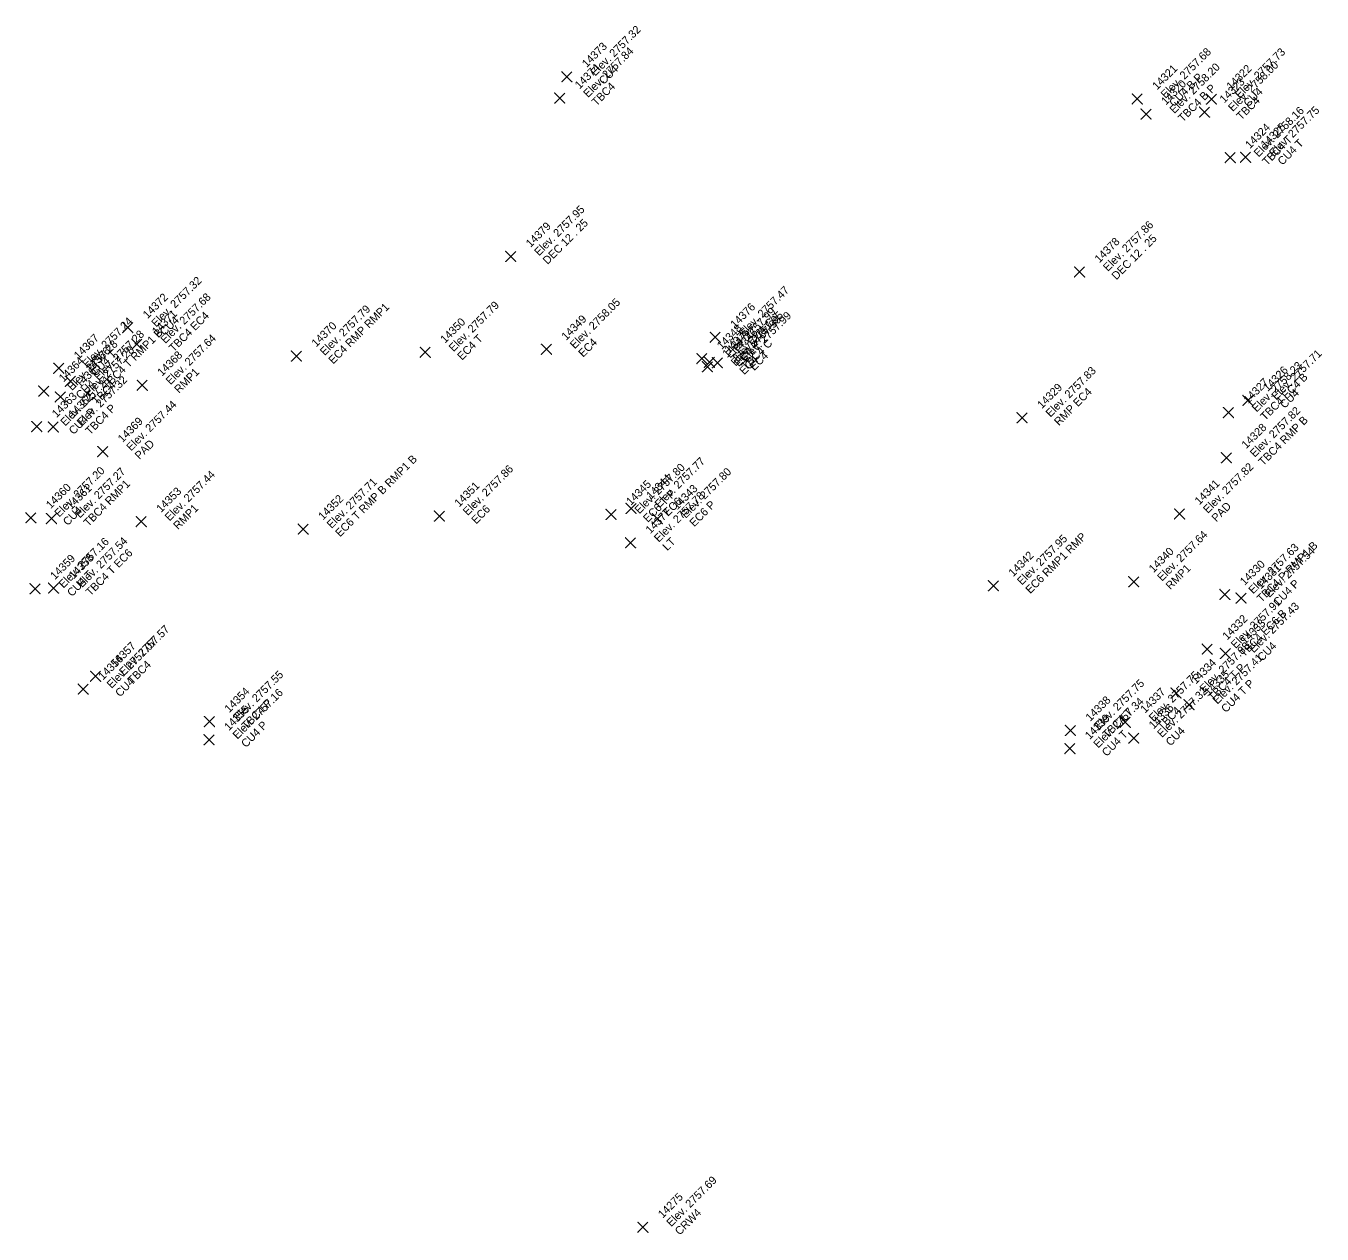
# Model space of a CAD drawing. Extents: x 2493999 to 2503109, y 700767 to 706646.
# Drawn here: x 2502364.97 to 2502403.84, y 703196.92 to 703233.16 of the extents above; entities that cross this region are included whole.
import ezdxf

# ---------------------------------------------------------------- set-up
doc = ezdxf.new("R2010")
doc.units = 0
doc.layers.add('ALG_CL_BLUE_Horiz', color=7, linetype='Continuous')
doc.layers.add('DES_SURFACE_Existing-Ground', color=7, linetype='Continuous')

msp = doc.modelspace()

# ---------------------------------------------------------------- linework, layer by layer
at = {"layer": 'ALG_CL_BLUE_Horiz'}
for points in [[(2502381.19, 703231.638), (2502381.04, 703231.788), (2502381.19, 703231.638), (2502381.04, 703231.488), (2502381.19, 703231.638), (2502381.34, 703231.488), (2502381.19, 703231.638), (2502381.34, 703231.788)], [(2502380.974, 703230.996), (2502380.824, 703231.146), (2502380.974, 703230.996), (2502380.824, 703230.846), (2502380.974, 703230.996), (2502381.124, 703230.846), (2502380.974, 703230.996), (2502381.124, 703231.146)], [(2502398.294, 703230.973), (2502398.144, 703231.123), (2502398.294, 703230.973), (2502398.144, 703230.823), (2502398.294, 703230.973), (2502398.444, 703230.823), (2502398.294, 703230.973), (2502398.444, 703231.123)], [(2502400.52, 703230.968), (2502400.37, 703231.118), (2502400.52, 703230.968), (2502400.37, 703230.818), (2502400.52, 703230.968), (2502400.67, 703230.818), (2502400.52, 703230.968), (2502400.67, 703231.118)], [(2502398.56, 703230.515), (2502398.41, 703230.665), (2502398.56, 703230.515), (2502398.41, 703230.365), (2502398.56, 703230.515), (2502398.71, 703230.365), (2502398.56, 703230.515), (2502398.71, 703230.665)], [(2502400.313, 703230.574), (2502400.163, 703230.724), (2502400.313, 703230.574), (2502400.163, 703230.424), (2502400.313, 703230.574), (2502400.463, 703230.424), (2502400.313, 703230.574), (2502400.463, 703230.724)], [(2502401.082, 703229.209), (2502400.932, 703229.359), (2502401.082, 703229.209), (2502400.932, 703229.059), (2502401.082, 703229.209), (2502401.232, 703229.059), (2502401.082, 703229.209), (2502401.232, 703229.359)], [(2502401.545, 703229.22), (2502401.395, 703229.37), (2502401.545, 703229.22), (2502401.395, 703229.07), (2502401.545, 703229.22), (2502401.695, 703229.07), (2502401.545, 703229.22), (2502401.695, 703229.37)], [(2502379.507, 703226.246), (2502379.357, 703226.396), (2502379.507, 703226.246), (2502379.357, 703226.096), (2502379.507, 703226.246), (2502379.657, 703226.096), (2502379.507, 703226.246), (2502379.657, 703226.396)], [(2502396.564, 703225.783), (2502396.414, 703225.933), (2502396.564, 703225.783), (2502396.414, 703225.633), (2502396.564, 703225.783), (2502396.714, 703225.633), (2502396.564, 703225.783), (2502396.714, 703225.933)], [(2502368.02, 703224.111), (2502367.87, 703224.261), (2502368.02, 703224.111), (2502367.87, 703223.961), (2502368.02, 703224.111), (2502368.17, 703223.961), (2502368.02, 703224.111), (2502368.17, 703224.261)], [(2502368.295, 703223.617), (2502368.145, 703223.767), (2502368.295, 703223.617), (2502368.145, 703223.467), (2502368.295, 703223.617), (2502368.445, 703223.467), (2502368.295, 703223.617), (2502368.445, 703223.767)], [(2502385.637, 703223.823), (2502385.487, 703223.973), (2502385.637, 703223.823), (2502385.487, 703223.673), (2502385.637, 703223.823), (2502385.787, 703223.673), (2502385.637, 703223.823), (2502385.787, 703223.973)], [(2502373.08, 703223.257), (2502372.93, 703223.407), (2502373.08, 703223.257), (2502372.93, 703223.107), (2502373.08, 703223.257), (2502373.23, 703223.107), (2502373.08, 703223.257), (2502373.23, 703223.407)], [(2502376.942, 703223.372), (2502376.792, 703223.522), (2502376.942, 703223.372), (2502376.792, 703223.222), (2502376.942, 703223.372), (2502377.092, 703223.222), (2502376.942, 703223.372), (2502377.092, 703223.522)], [(2502380.575, 703223.461), (2502380.425, 703223.611), (2502380.575, 703223.461), (2502380.425, 703223.311), (2502380.575, 703223.461), (2502380.725, 703223.311), (2502380.575, 703223.461), (2502380.725, 703223.611)], [(2502385.237, 703223.182), (2502385.087, 703223.332), (2502385.237, 703223.182), (2502385.087, 703223.032), (2502385.237, 703223.182), (2502385.387, 703223.032), (2502385.237, 703223.182), (2502385.387, 703223.332)], [(2502365.952, 703222.892), (2502365.802, 703223.042), (2502365.952, 703222.892), (2502365.802, 703222.742), (2502365.952, 703222.892), (2502366.102, 703222.742), (2502365.952, 703222.892), (2502366.102, 703223.042)], [(2502385.403, 703222.939), (2502385.253, 703223.089), (2502385.403, 703222.939), (2502385.253, 703222.789), (2502385.403, 703222.939), (2502385.553, 703222.789), (2502385.403, 703222.939), (2502385.553, 703223.089)], [(2502385.462, 703223.071), (2502385.312, 703223.221), (2502385.462, 703223.071), (2502385.312, 703222.921), (2502385.462, 703223.071), (2502385.612, 703222.921), (2502385.462, 703223.071), (2502385.612, 703223.221)], [(2502385.705, 703223.06), (2502385.555, 703223.21), (2502385.705, 703223.06), (2502385.555, 703222.91), (2502385.705, 703223.06), (2502385.855, 703222.91), (2502385.705, 703223.06), (2502385.855, 703223.21)], [(2502366.299, 703222.504), (2502366.149, 703222.654), (2502366.299, 703222.504), (2502366.149, 703222.354), (2502366.299, 703222.504), (2502366.449, 703222.354), (2502366.299, 703222.504), (2502366.449, 703222.654)], [(2502368.454, 703222.381), (2502368.304, 703222.531), (2502368.454, 703222.381), (2502368.304, 703222.231), (2502368.454, 703222.381), (2502368.604, 703222.231), (2502368.454, 703222.381), (2502368.604, 703222.531)], [(2502365.502, 703222.207), (2502365.352, 703222.357), (2502365.502, 703222.207), (2502365.352, 703222.057), (2502365.502, 703222.207), (2502365.652, 703222.057), (2502365.502, 703222.207), (2502365.652, 703222.357)], [(2502365.998, 703222.031), (2502365.848, 703222.181), (2502365.998, 703222.031), (2502365.848, 703221.881), (2502365.998, 703222.031), (2502366.148, 703221.881), (2502365.998, 703222.031), (2502366.148, 703222.181)], [(2502401.613, 703221.926), (2502401.463, 703222.076), (2502401.613, 703221.926), (2502401.463, 703221.776), (2502401.613, 703221.926), (2502401.763, 703221.776), (2502401.613, 703221.926), (2502401.763, 703222.076)], [(2502394.842, 703221.41), (2502394.692, 703221.56), (2502394.842, 703221.41), (2502394.692, 703221.26), (2502394.842, 703221.41), (2502394.992, 703221.26), (2502394.842, 703221.41), (2502394.992, 703221.56)], [(2502401.028, 703221.562), (2502400.878, 703221.712), (2502401.028, 703221.562), (2502400.878, 703221.412), (2502401.028, 703221.562), (2502401.178, 703221.412), (2502401.028, 703221.562), (2502401.178, 703221.712)], [(2502365.293, 703221.141), (2502365.143, 703221.291), (2502365.293, 703221.141), (2502365.143, 703220.991), (2502365.293, 703221.141), (2502365.443, 703220.991), (2502365.293, 703221.141), (2502365.443, 703221.291)], [(2502365.787, 703221.134), (2502365.637, 703221.284), (2502365.787, 703221.134), (2502365.637, 703220.984), (2502365.787, 703221.134), (2502365.937, 703220.984), (2502365.787, 703221.134), (2502365.937, 703221.284)], [(2502367.271, 703220.394), (2502367.121, 703220.544), (2502367.271, 703220.394), (2502367.121, 703220.244), (2502367.271, 703220.394), (2502367.421, 703220.244), (2502367.271, 703220.394), (2502367.421, 703220.544)], [(2502400.971, 703220.208), (2502400.821, 703220.358), (2502400.971, 703220.208), (2502400.821, 703220.058), (2502400.971, 703220.208), (2502401.121, 703220.058), (2502400.971, 703220.208), (2502401.121, 703220.358)], [(2502377.365, 703218.46), (2502377.215, 703218.61), (2502377.365, 703218.46), (2502377.215, 703218.31), (2502377.365, 703218.46), (2502377.515, 703218.31), (2502377.365, 703218.46), (2502377.515, 703218.61)], [(2502382.515, 703218.507), (2502382.365, 703218.657), (2502382.515, 703218.507), (2502382.365, 703218.357), (2502382.515, 703218.507), (2502382.665, 703218.357), (2502382.515, 703218.507), (2502382.665, 703218.657)], [(2502383.116, 703218.691), (2502382.966, 703218.841), (2502383.116, 703218.691), (2502382.966, 703218.541), (2502383.116, 703218.691), (2502383.266, 703218.541), (2502383.116, 703218.691), (2502383.266, 703218.841)], [(2502399.564, 703218.525), (2502399.414, 703218.675), (2502399.564, 703218.525), (2502399.414, 703218.375), (2502399.564, 703218.525), (2502399.714, 703218.375), (2502399.564, 703218.525), (2502399.714, 703218.675)], [(2502365.116, 703218.41), (2502364.966, 703218.56), (2502365.116, 703218.41), (2502364.966, 703218.26), (2502365.116, 703218.41), (2502365.266, 703218.26), (2502365.116, 703218.41), (2502365.266, 703218.56)], [(2502365.733, 703218.383), (2502365.583, 703218.533), (2502365.733, 703218.383), (2502365.583, 703218.233), (2502365.733, 703218.383), (2502365.883, 703218.233), (2502365.733, 703218.383), (2502365.883, 703218.533)], [(2502368.425, 703218.294), (2502368.275, 703218.444), (2502368.425, 703218.294), (2502368.275, 703218.144), (2502368.425, 703218.294), (2502368.575, 703218.144), (2502368.425, 703218.294), (2502368.575, 703218.444)], [(2502373.283, 703218.07), (2502373.133, 703218.22), (2502373.283, 703218.07), (2502373.133, 703217.92), (2502373.283, 703218.07), (2502373.433, 703217.92), (2502373.283, 703218.07), (2502373.433, 703218.22)], [(2502383.907, 703218.377), (2502383.757, 703218.527), (2502383.907, 703218.377), (2502383.757, 703218.227), (2502383.907, 703218.377), (2502384.057, 703218.227), (2502383.907, 703218.377), (2502384.057, 703218.527)], [(2502383.099, 703217.658), (2502382.949, 703217.808), (2502383.099, 703217.658), (2502382.949, 703217.508), (2502383.099, 703217.658), (2502383.249, 703217.508), (2502383.099, 703217.658), (2502383.249, 703217.808)], [(2502365.242, 703216.281), (2502365.092, 703216.431), (2502365.242, 703216.281), (2502365.092, 703216.131), (2502365.242, 703216.281), (2502365.392, 703216.131), (2502365.242, 703216.281), (2502365.392, 703216.431)], [(2502365.797, 703216.3), (2502365.647, 703216.45), (2502365.797, 703216.3), (2502365.647, 703216.15), (2502365.797, 703216.3), (2502365.947, 703216.15), (2502365.797, 703216.3), (2502365.947, 703216.45)], [(2502393.983, 703216.372), (2502393.833, 703216.522), (2502393.983, 703216.372), (2502393.833, 703216.222), (2502393.983, 703216.372), (2502394.133, 703216.222), (2502393.983, 703216.372), (2502394.133, 703216.522)], [(2502398.189, 703216.492), (2502398.039, 703216.642), (2502398.189, 703216.492), (2502398.039, 703216.342), (2502398.189, 703216.492), (2502398.339, 703216.342), (2502398.189, 703216.492), (2502398.339, 703216.642)], [(2502400.923, 703216.108), (2502400.773, 703216.258), (2502400.923, 703216.108), (2502400.773, 703215.958), (2502400.923, 703216.108), (2502401.073, 703215.958), (2502400.923, 703216.108), (2502401.073, 703216.258)], [(2502401.41, 703215.998), (2502401.26, 703216.148), (2502401.41, 703215.998), (2502401.26, 703215.848), (2502401.41, 703215.998), (2502401.56, 703215.848), (2502401.41, 703215.998), (2502401.56, 703216.148)], [(2502400.397, 703214.471), (2502400.247, 703214.621), (2502400.397, 703214.471), (2502400.247, 703214.321), (2502400.397, 703214.471), (2502400.547, 703214.321), (2502400.397, 703214.471), (2502400.547, 703214.621)], [(2502400.937, 703214.342), (2502400.787, 703214.492), (2502400.937, 703214.342), (2502400.787, 703214.192), (2502400.937, 703214.342), (2502401.087, 703214.192), (2502400.937, 703214.342), (2502401.087, 703214.492)], [(2502367.055, 703213.654), (2502366.905, 703213.804), (2502367.055, 703213.654), (2502366.905, 703213.504), (2502367.055, 703213.654), (2502367.205, 703213.504), (2502367.055, 703213.654), (2502367.205, 703213.804)], [(2502366.684, 703213.272), (2502366.534, 703213.422), (2502366.684, 703213.272), (2502366.534, 703213.122), (2502366.684, 703213.272), (2502366.834, 703213.122), (2502366.684, 703213.272), (2502366.834, 703213.422)], [(2502399.458, 703213.151), (2502399.308, 703213.301), (2502399.458, 703213.151), (2502399.308, 703213.001), (2502399.458, 703213.151), (2502399.608, 703213.001), (2502399.458, 703213.151), (2502399.608, 703213.301)], [(2502399.851, 703212.801), (2502399.701, 703212.951), (2502399.851, 703212.801), (2502399.701, 703212.651), (2502399.851, 703212.801), (2502400.001, 703212.651), (2502399.851, 703212.801), (2502400.001, 703212.951)], [(2502370.471, 703212.294), (2502370.321, 703212.444), (2502370.471, 703212.294), (2502370.321, 703212.144), (2502370.471, 703212.294), (2502370.621, 703212.144), (2502370.471, 703212.294), (2502370.621, 703212.444)], [(2502397.936, 703212.277), (2502397.786, 703212.427), (2502397.936, 703212.277), (2502397.786, 703212.127), (2502397.936, 703212.277), (2502398.086, 703212.127), (2502397.936, 703212.277), (2502398.086, 703212.427)], [(2502396.293, 703212.032), (2502396.143, 703212.182), (2502396.293, 703212.032), (2502396.143, 703211.882), (2502396.293, 703212.032), (2502396.443, 703211.882), (2502396.293, 703212.032), (2502396.443, 703212.182)], [(2502370.46, 703211.753), (2502370.31, 703211.903), (2502370.46, 703211.753), (2502370.31, 703211.603), (2502370.46, 703211.753), (2502370.61, 703211.603), (2502370.46, 703211.753), (2502370.61, 703211.903)], [(2502396.274, 703211.488), (2502396.124, 703211.638), (2502396.274, 703211.488), (2502396.124, 703211.338), (2502396.274, 703211.488), (2502396.424, 703211.338), (2502396.274, 703211.488), (2502396.424, 703211.638)], [(2502398.188, 703211.801), (2502398.038, 703211.951), (2502398.188, 703211.801), (2502398.038, 703211.651), (2502398.188, 703211.801), (2502398.338, 703211.651), (2502398.188, 703211.801), (2502398.338, 703211.951)], [(2502383.469, 703197.131), (2502383.319, 703197.281), (2502383.469, 703197.131), (2502383.319, 703196.981), (2502383.469, 703197.131), (2502383.619, 703196.981), (2502383.469, 703197.131), (2502383.619, 703197.281)]]:
    msp.add_lwpolyline(points, dxfattribs=at)

# ---------------------------------------------------------------- texts
at = {"layer": 'DES_SURFACE_Existing-Ground'}
for s, p in [('Elev. 2757.32', (2502382.039, 703231.638)), ('14373', (2502381.784, 703231.893)), ('Elev. 2757.84', (2502381.823, 703230.996)), ('Elev. 2757.68', (2502399.143, 703230.973)), ('Elev. 2757.73', (2502401.369, 703230.968)), ('14374', (2502381.568, 703231.251)), ('CU4', (2502382.293, 703231.383)), ('14321', (2502398.888, 703231.228)), ('Elev. 2758.20', (2502399.409, 703230.515)), ('14322', (2502401.114, 703231.223)), ('Elev. 2758.00', (2502401.162, 703230.574)), ('TBC4', (2502382.077, 703230.741)), ('14320', (2502399.154, 703230.77)), ('CU4 B P', (2502399.397, 703230.718)), ('14323', (2502400.907, 703230.829)), ('TBC4 B P', (2502399.663, 703230.26)), ('CU4', (2502401.623, 703230.713)), ('TBC4', (2502401.416, 703230.319)), ('Elev. 2758.16', (2502401.931, 703229.209)), ('Elev. 2757.75', (2502402.394, 703229.22)), ('14324', (2502401.676, 703229.464)), ('14325', (2502402.139, 703229.475)), ('TBC4 T', (2502402.185, 703228.954)), ('CU4 T', (2502402.648, 703228.965)), ('Elev. 2757.95', (2502380.356, 703226.246)), ('14379', (2502380.101, 703226.501)), ('DEC 12 . 25', (2502380.61, 703225.991)), ('Elev. 2757.86', (2502397.413, 703225.783)), ('14378', (2502397.158, 703226.038)), ('DEC 12 . 25', (2502397.667, 703225.528)), ('Elev. 2757.32', (2502368.869, 703224.111)), ('Elev. 2757.47', (2502386.486, 703223.823)), ('14372', (2502368.614, 703224.366)), ('Elev. 2757.68', (2502369.144, 703223.617)), ('Elev. 2757.79', (2502377.791, 703223.372)), ('Elev. 2758.05', (2502381.424, 703223.461)), ('14376', (2502386.231, 703224.078)), ('14371', (2502368.889, 703223.872)), ('CU4', (2502369.123, 703223.856)), ('TBC4 EC4', (2502369.398, 703223.362)), ('Elev. 2757.79', (2502373.929, 703223.257)), ('EC4 RMP RMP1', (2502374.183, 703223.002)), ('14349', (2502381.169, 703223.716)), ('Elev. 2757.99', (2502386.086, 703223.182)), ('Elev. 2757.99', (2502386.252, 703222.939)), ('Elev. 2757.95', (2502386.311, 703223.071)), ('Elev. 2757.99', (2502386.554, 703223.06)), ('Elev. 2757.24', (2502366.801, 703222.892)), ('TBC4 T RMP1 B', (2502367.402, 703222.249)), ('14370', (2502373.674, 703223.512)), ('14350', (2502377.536, 703223.627)), ('14348', (2502385.831, 703223.437)), ('14375', (2502386.056, 703223.326)), ('14346', (2502386.299, 703223.315)), ('CU4 C', (2502386.74, 703223.568)), ('Elev. 2757.28', (2502366.351, 703222.207)), ('14367', (2502366.546, 703223.147)), ('Elev. 2757.28', (2502367.148, 703222.504)), ('Elev. 2757.64', (2502369.303, 703222.381)), ('EC4 T', (2502378.045, 703223.117)), ('EC4', (2502381.678, 703223.206)), ('14347', (2502385.997, 703223.194)), ('EC4 P', (2502386.34, 703222.927)), ('TBC4 C', (2502386.565, 703222.816)), ('Elev. 2757.28', (2502366.847, 703222.031)), ('14366', (2502366.893, 703222.759)), ('CU4 T', (2502367.055, 703222.637)), ('14368', (2502369.048, 703222.636)), ('EC4', (2502386.808, 703222.805)), ('Elev. 2757.71', (2502402.462, 703221.926)), ('14364', (2502366.096, 703222.462)), ('14365', (2502366.592, 703222.286)), ('EC4', (2502386.506, 703222.684)), ('Elev. 2757.83', (2502395.691, 703221.41)), ('Elev. 2758.23', (2502401.877, 703221.562)), ('14326', (2502402.207, 703222.181)), ('Elev. 2757.21', (2502366.142, 703221.141)), ('Elev. 2757.32', (2502366.636, 703221.134)), ('CU4', (2502366.605, 703221.952)), ('TBC4', (2502367.101, 703221.776)), ('RMP1', (2502369.557, 703222.126)), ('14327', (2502401.622, 703221.817)), ('TBC4 EC4 B', (2502402.131, 703221.307)), ('14363', (2502365.887, 703221.396)), ('14362', (2502366.381, 703221.389)), ('14329', (2502395.436, 703221.665)), ('RMP EC4', (2502395.945, 703221.155)), ('CU4', (2502402.716, 703221.671)), ('TBC4 P', (2502366.89, 703220.879)), ('Elev. 2757.44', (2502368.12, 703220.394)), ('Elev. 2757.82', (2502401.82, 703220.208)), ('CU4 P', (2502366.396, 703220.886)), ('14369', (2502367.865, 703220.649)), ('TBC4 RMP B', (2502402.074, 703219.953)), ('14328', (2502401.565, 703220.463)), ('PAD', (2502368.374, 703220.139)), ('EC6 T RMP B RMP1 B', (2502374.386, 703217.815)), ('Elev. 2757.77', (2502383.965, 703218.691)), ('Elev. 2757.20', (2502365.965, 703218.41)), ('Elev. 2757.27', (2502366.582, 703218.383)), ('Elev. 2757.44', (2502369.274, 703218.294)), ('Elev. 2757.86', (2502378.214, 703218.46)), ('Elev. 2757.80', (2502383.364, 703218.507)), ('Elev. 2757.80', (2502384.756, 703218.377)), ('Elev. 2757.82', (2502400.413, 703218.525)), ('14360', (2502365.71, 703218.665)), ('14361', (2502366.327, 703218.638)), ('TBC4 RMP1', (2502366.836, 703218.128)), ('Elev. 2757.71', (2502374.132, 703218.07)), ('14351', (2502377.959, 703218.715)), ('14345', (2502383.109, 703218.762)), ('14344', (2502383.71, 703218.946)), ('14343', (2502384.501, 703218.632)), ('14341', (2502400.158, 703218.78)), ('14353', (2502369.019, 703218.549)), ('14352', (2502373.877, 703218.325)), ('EC6 T P', (2502383.618, 703218.252)), ('Elev. 2757.78', (2502383.948, 703217.658)), ('EC6', (2502384.219, 703218.436)), ('CU4', (2502366.219, 703218.155)), ('RMP1', (2502369.528, 703218.039)), ('EC6', (2502378.468, 703218.205)), ('14377', (2502383.693, 703217.913)), ('EC6 P', (2502385.01, 703218.122)), ('PAD', (2502400.667, 703218.27)), ('LT', (2502384.202, 703217.403)), ('Elev. 2757.95', (2502394.832, 703216.372)), ('EC6 RMP1 RMP', (2502395.086, 703216.117)), ('Elev. 2757.64', (2502399.038, 703216.492)), ('Elev. 2757.16', (2502366.091, 703216.281)), ('Elev. 2757.54', (2502366.646, 703216.3)), ('TBC4 T EC6', (2502366.9, 703216.045)), ('14340', (2502398.783, 703216.747)), ('Elev. 2757.63', (2502401.772, 703216.108)), ('TBC4 P RMP1 B', (2502402.026, 703215.853)), ('Elev. 2757.54', (2502402.259, 703215.998)), ('14359', (2502365.836, 703216.536)), ('14358', (2502366.391, 703216.555)), ('14342', (2502394.577, 703216.627)), ('14330', (2502401.517, 703216.363)), ('CU4 T', (2502366.345, 703216.026)), ('RMP1', (2502399.292, 703216.237)), ('14331', (2502402.004, 703216.253)), ('CU4 P', (2502402.513, 703215.743)), ('Elev. 2757.91', (2502401.246, 703214.471)), ('TBC4 EC6 B', (2502401.5, 703214.216)), ('Elev. 2757.43', (2502401.786, 703214.342)), ('Elev. 2757.57', (2502367.904, 703213.654)), ('14332', (2502400.991, 703214.726)), ('14333', (2502401.531, 703214.597)), ('Elev. 2757.07', (2502367.533, 703213.272)), ('14357', (2502367.649, 703213.909)), ('Elev. 2757.88', (2502400.307, 703213.151)), ('CU4', (2502402.04, 703214.087)), ('14356', (2502367.278, 703213.527)), ('TBC4', (2502368.158, 703213.399)), ('14334', (2502400.052, 703213.406)), ('TBC4 T P', (2502400.561, 703212.896)), ('Elev. 2757.41', (2502400.7, 703212.801)), ('CU4', (2502367.787, 703213.017)), ('Elev. 2757.55', (2502371.32, 703212.294)), ('Elev. 2757.75', (2502397.142, 703212.032)), ('Elev. 2757.75', (2502398.785, 703212.277)), ('14335', (2502400.445, 703213.056)), ('14354', (2502371.065, 703212.549)), ('Elev. 2757.16', (2502371.309, 703211.753)), ('14337', (2502398.53, 703212.532)), ('Elev. 2757.32', (2502399.037, 703211.801)), ('CU4 T P', (2502400.954, 703212.546)), ('14355', (2502371.054, 703212.008)), ('TBC4 P', (2502371.574, 703212.039)), ('14338', (2502396.887, 703212.287)), ('Elev. 2757.34', (2502397.123, 703211.488)), ('14336', (2502398.782, 703212.056)), ('14339', (2502396.868, 703211.743)), ('TBC4 T', (2502397.396, 703211.777)), ('TBC4', (2502399.039, 703212.022)), ('CU4 P', (2502371.563, 703211.498)), ('CU4 T', (2502397.377, 703211.233)), ('CU4', (2502399.291, 703211.546)), ('Elev. 2757.69', (2502384.318, 703197.131)), ('14275', (2502384.063, 703197.386)), ('CRW4', (2502384.572, 703196.876))]:
    msp.add_text(s, height=0.24, rotation=45, dxfattribs=at).set_placement(p)

doc.saveas('drawing.dxf')
